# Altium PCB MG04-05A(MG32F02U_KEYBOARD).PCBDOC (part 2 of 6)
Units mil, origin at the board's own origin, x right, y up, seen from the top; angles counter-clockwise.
Board outline 17912.8 x 10422.68 mil, 2 copper layers (Top Layer, Bottom Layer); 623 components, 347 nets, 1816 pads, 821 vias.
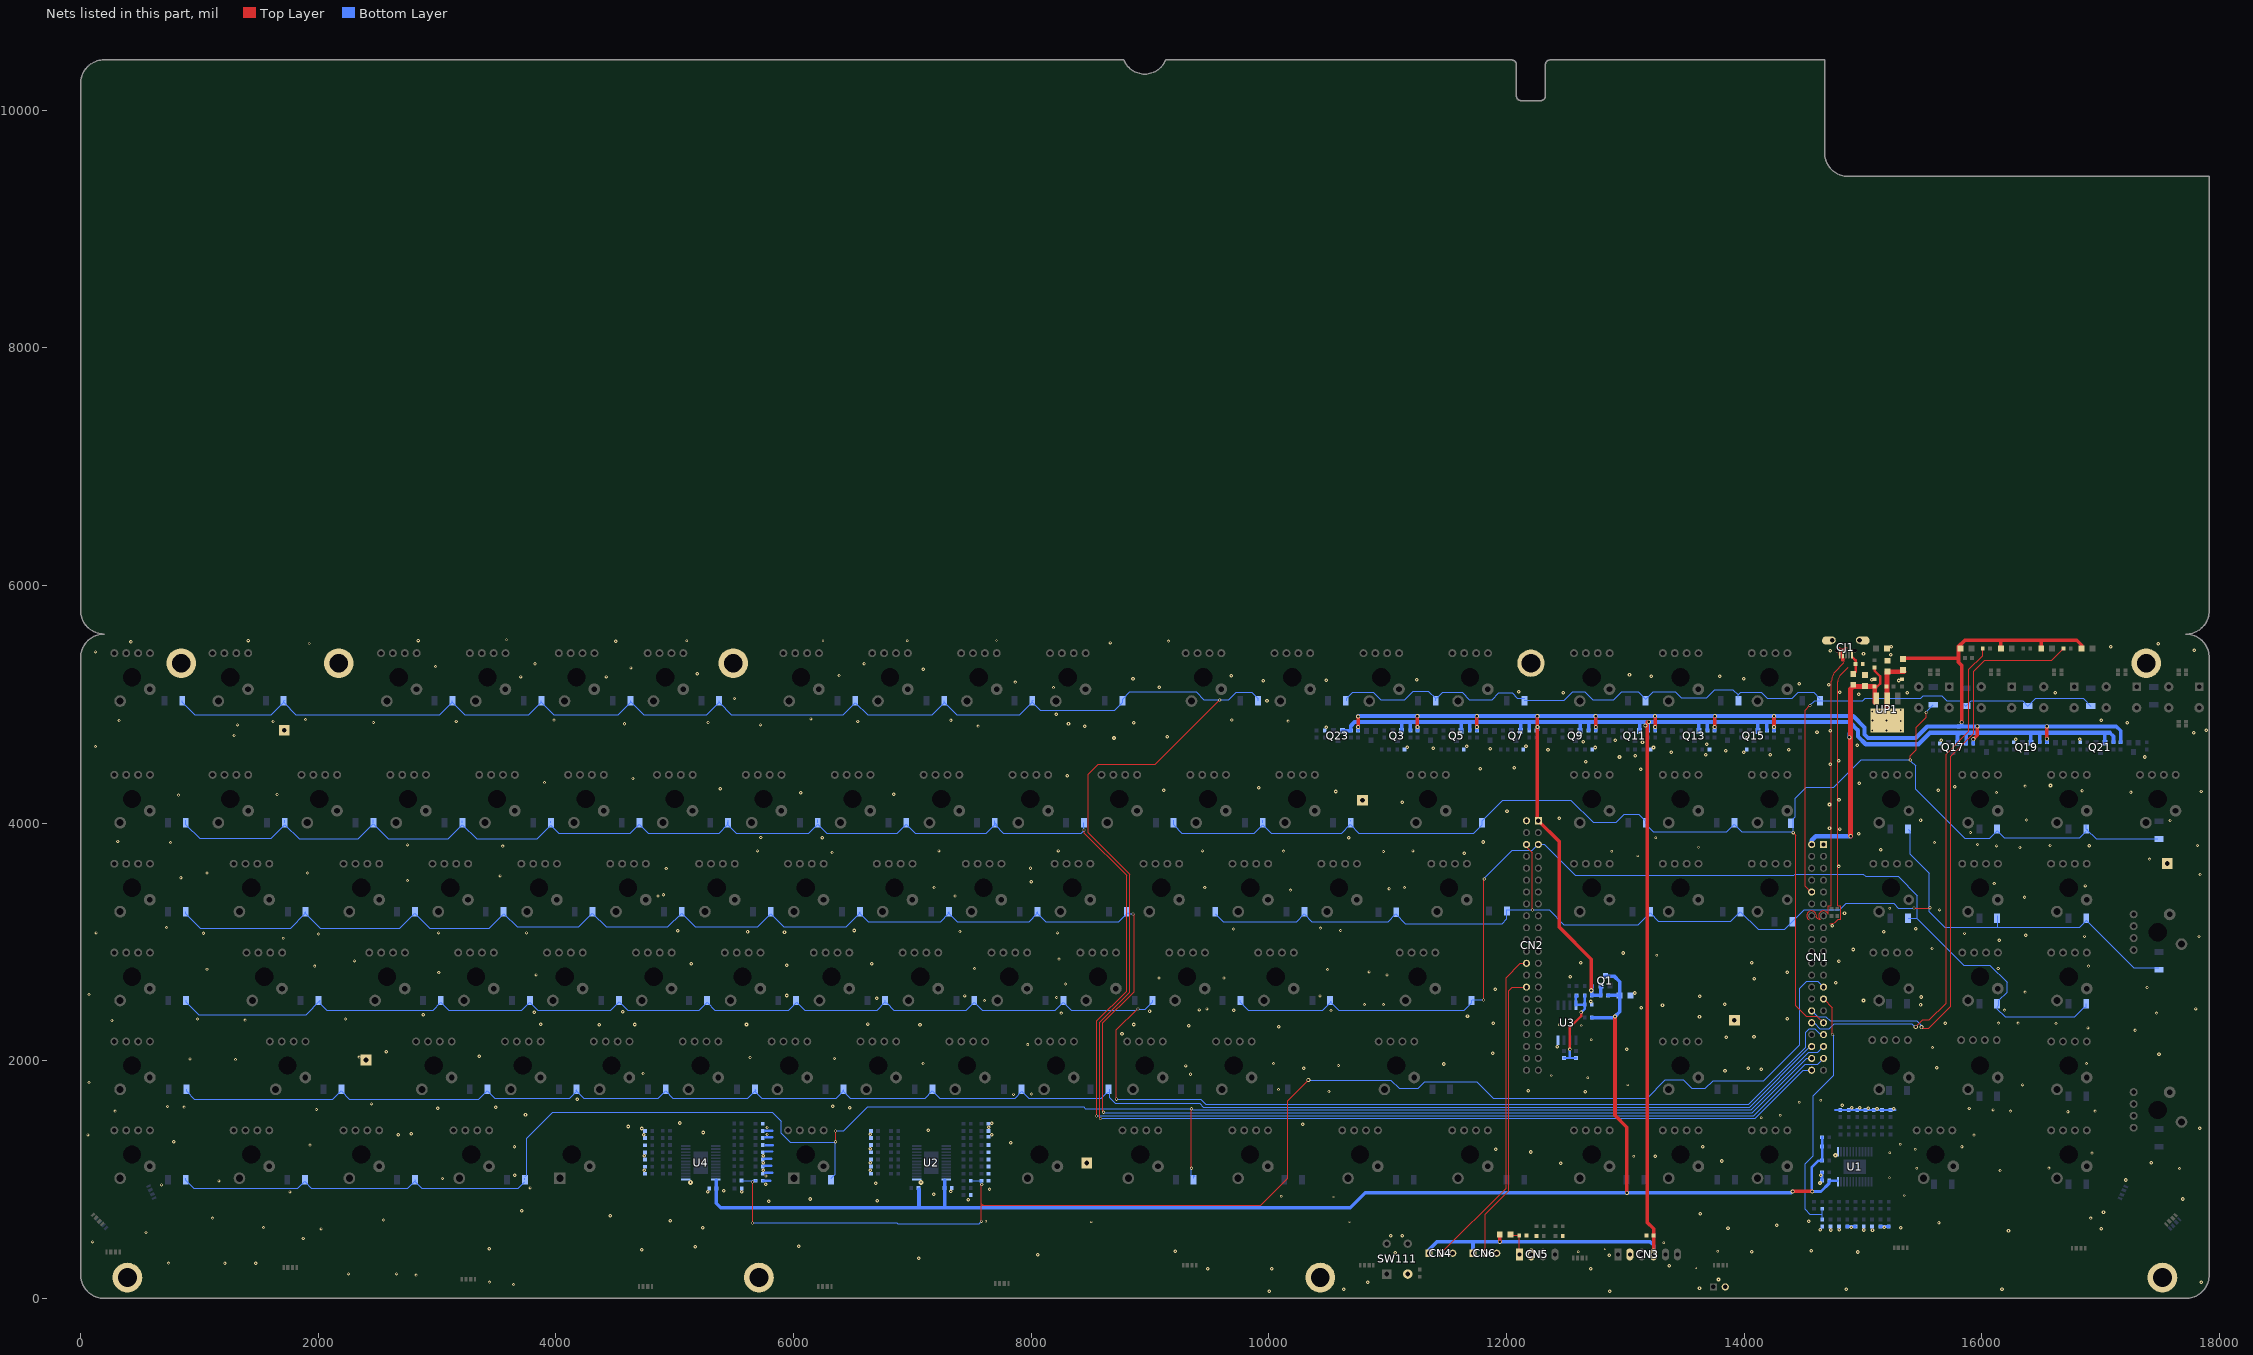
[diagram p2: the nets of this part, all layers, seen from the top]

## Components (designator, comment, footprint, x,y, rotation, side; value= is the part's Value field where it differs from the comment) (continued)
SW72 "SW_PB_SPST" SW2_KS4B#1 13463.65,4203.29 r0 top locked (schematic designator Home)
SW73 "SW_PB_SPST" SW2_KS4B#1 14211.65,4203.29 r0 top locked (schematic designator "Page Up")
SW74 "SW_PB_SPST" SW2_KS4B#1 15983.52,4203.29 r0 top locked (schematic designator N/)
SW75 "SW_PB_SPST" SW2_KS4B#1 16731.35,4203.29 r0 top locked (schematic designator N*)
SW76 "SW_PB_SPST" SW2_KS4B#1 17479.41,4203.29 r0 top locked (schematic designator N-)
SW77 "SW_PB_SPST" SW2_KS4B#1 9093.57,3454.89 r0 top locked (schematic designator P)
SW78 "SW_PB_SPST" SW2_KS4B#1 9841.6,3454.89 r0 top locked (schematic designator [{)
SW79 "SW_PB_SPST" SW2_KS4B#1 10589.63,3454.89 r0 top locked (schematic designator ]})
SW80 "SW_PB_SPST" SW2_KS4B#1 11514.79,3454.89 r0 top locked (schematic designator \)
SW81 "SW_PB_SPST" SW2_KS4B#1 12715.58,3454.89 r0 top locked (schematic designator Delete)
SW82 "SW_PB_SPST" SW2_KS4B#1 13463.65,3454.89 r0 top locked (schematic designator END)
SW83 "SW_PB_SPST" SW2_KS4B#3 14211.65,3454.89 r0 top locked (schematic designator "Page Down")
SW84 "SW_PB_SPST" SW2_KS4B#3 15235.27,4203.29 r0 top locked (schematic designator "Num Lock")
SW85 "SW_PB_SPST" SW2_KS4B#1 15983.34,3454.89 r0 top locked (schematic designator N8)
SW86 "SW_PB_SPST" SW2_KS4B#1 16730.57,3454.89 r0 top locked (schematic designator N9)
SW87 "SW_PB_SPST" SW2_KS4B#1 17479.6,3081.25 r90 top (schematic designator N+)
SW88 "SW_PB_SPST" SW2_KS4B#1 9310.11,2707.29 r0 top locked (schematic designator ;:)
SW89 "SW_PB_SPST" SW2_KS4B#1 10058.14,2707.29 r0 top locked (schematic designator "'\"")
SW90 "SW_PB_SPST" SW2_KS4B#1 11249.08,2707.29 r0 top locked (schematic designator Enter)
SW91 "SW_PB_SPST" SW2_KS4B#3 15234.49,3454.89 r0 top locked (schematic designator N7)
SW92 "SW_PB_SPST" SW2_KS4B#1 15983.52,2707.29 r0 top locked (schematic designator N5)
SW93 "SW_PB_SPST" SW2_KS4B#1 16731.57,2707.29 r0 top locked (schematic designator N6)
SW94 "SW_PB_SPST" SW2_KS4B#1 8955.75,1959.19 r0 top locked (schematic designator .>)
SW95 "SW_PB_SPST" SW2_KS4B#1 9703.78,1959.19 r0 top locked (schematic designator /1)
SW96 "SW_PB_SPST" SW2_KS4B#1 11071.89,1959.19 r0 top locked (schematic designator R-SHIFT)
SW97 "SW_PB_SPST" SW2_KS4B#1 13463.65,1959.19 r0 top locked (schematic designator UP-L)
SW98 "SW_PB_SPST" SW2_KS4B#3 15234.84,2707.29 r0 top locked (schematic designator N4)
SW99 "SW_PB_SPST" SW2_KS4B#1 15983.5,1959.19 r0 top locked (schematic designator N2)
SW100 "SW_PB_SPST" SW2_KS4B#1 16731.36,1959.19 r0 top locked (schematic designator N3)
SW101 "SW_PB_SPST" SW2_KS4B#1 17479.4,1585.19 r90 top locked (schematic designator N-Enter)
SW102 "SW_PB_SPST" SW2_KS4B#1 9840.58,1211.19 r0 top locked (schematic designator FN)
SW103 "SW_PB_SPST" SW2_KS4B#1 10765.78,1211.19 r0 top locked (schematic designator APP)
SW104 "SW_PB_SPST" SW2_KS4B#1 11690.98,1211.19 r0 top locked (schematic designator R-Ctrl)
SW105 "SW_PB_SPST" SW2_KS4B#1 12715.58,1211.19 r0 top locked (schematic designator Left-L)
SW106 "SW_PB_SPST" SW2_KS4B#1 13463.65,1211.19 r0 top locked (schematic designator Down-L)
SW107 "SW_PB_SPST" SW2_KS4B#1 14211.65,1211.19 r0 top locked (schematic designator Right-L)
SW108 "SW_PB_SPST" SW2_KS4B#1 15235.47,1959.19 r0 top locked (schematic designator N1)
SW109 "SW_PB_SPST" SW2_KS4B#1 15609.49,1211.19 r0 top locked (schematic designator N0)
SW110 "SW_PB_SPST" SW2_KS4B#1 16731.54,1211.19 r0 top locked (schematic designator .DEL)
SW111 "SW1_4P" SW-TACT-P4.5X6.5-Z6.2X6.2X5#2 10991,204.63 r90 bottom locked
SW112 "SW_PB_SPST" SW2_KS4B#2 4132.9,1211.19 r0 top locked (schematic designator Space3)
SW113 "SW_PB_SPST" SW2_KS4B#1 8069.91,1211.19 r0 top locked (schematic designator Space2)
TP1 "TP-Gold" SIP1-39 2401.17,2006.36 r0 top
TP2 "TP-Gold" SIP1-39 1712.2,4781.95 r0 top
TP3 "TP-Gold" SIP1-39 8467,1140 r0 top
TP4 "TP-Gold" SIP1-39 17558.66,3659.9 r0 top
TP5 "TP-Gold" SIP1-39 13916.92,2341 r0 top
TP6 "TP-Gold" SIP1-39 10787,4191.4 r0 top
U1 "TLC5948A" SOP24-P0.65-W6.4-PAD 14789.25,1234.89 r0 bottom locked
U2 "TLC5948A" SOP24-P0.65-W6.4-PAD 7034.02,999.89 r90 bottom locked
U3 "MX25LXX-SOP" SOP8-P1.27-W6.2+8.1 12583.22,2171.26 r180 bottom
U4 "TLC5948A" SOP24-P0.65-W6.4-PAD 5094.02,999.89 r90 bottom locked
UP1 "AP1117-ADJ" SOT223H\3P 15202,4920 r180 top

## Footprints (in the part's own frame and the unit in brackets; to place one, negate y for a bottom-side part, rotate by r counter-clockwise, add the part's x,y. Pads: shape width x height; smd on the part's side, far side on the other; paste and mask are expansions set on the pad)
C-0603 [mil]
  rect 32x32 smd: 1(-30,0) 2(30,0)
  silkscreen extent -60,-26 60,26
C-0805 [mil]
  rect 50x50 smd: 1(-46,0) 2(46,0)
  silkscreen extent -90,-40 90,40
D-0805 [mil]
  rect 50x50 smd: 1(0,46) 2(0,-46)
  silkscreen extent -40,-85 40,85
DIODE_DO213AA [mm]
  rect 1.25x2 smd: 1(-1.9,0) 2(1.9,0)
  silkscreen extent -2.6,-1.1 3,1.1
HD4-P2.54-Z12.4X5.7X7-UL [mil]
  rect 60x100 hole 35: 1(-150,0)
  oval 60x100 hole 35: 2(-50,0) 3(50,0) 4(150,0)
  silkscreen extent -246,-130 245,118
HD6-P2.54-UL [mil]
  rect 60x100 hole 35: 1(-250,0)
  oval 60x100 hole 35: 2(-150,0) 3(-50,0) 4(50,0) 5(150,0) 6(250,0)
  silkscreen extent -344,-130 346,127
HD20X2-P2.54 [mil]
  rect 60x60 hole 37: 1(0,0)
  round 60 hole 37: 2(0,100) 3(100,0) 4(100,100) 5(200,0) 6(200,100) 7(300,0) 8(300,100) 9(400,0) 10(400,100) 11(500,0) 12(500,100) 13(600,0) 14(600,100) 15(700,0) 16(700,100) 17(800,0) 18(800,100) 19(900,0) 20(900,100) 21(1000,0) 22(1000,100) 23(1100,0) 24(1100,100) 25(1200,0) 26(1200,100) 27(1300,0) 28(1300,100) 29(1400,0) 30(1400,100) 31(1500,0) 32(1500,100) 33(1600,0) 34(1600,100) 35(1700,0) 36(1700,100) 37(1800,0) 38(1800,100) 39(1900,0) 40(1900,100)
  silkscreen extent -50,-73 1960,150
HD22X2-P2.54 [mil]
  rect 60x60 hole 37: 1(0,0)
  round 60 hole 37: 2(0,100) 3(100,0) 4(100,100) 5(200,0) 6(200,100) 7(300,0) 8(300,100) 9(400,0) 10(400,100) 11(500,0) 12(500,100) 13(600,0) 14(600,100) 15(700,0) 16(700,100) 17(800,0) 18(800,100) 19(900,0) 20(900,100) 21(1000,0) 22(1000,100) 23(1100,0) 24(1100,100) 25(1200,0) 26(1200,100) 27(1300,0) 28(1300,100) 29(1400,0) 30(1400,100) 31(1500,0) 32(1500,100) 33(1600,0) 34(1600,100) 35(1700,0) 36(1700,100) 37(1800,0) 38(1800,100) 39(1900,0) 40(1900,100) 41(2000,0) 42(2000,100) 43(2100,0) 44(2100,100)
  silkscreen extent -50,-73 2160,150
L-0603 [mil]
  rect 32x32 smd: 1(-30,0) 2(30,0)
  silkscreen extent -55,-25 55,25
LED4P_SMD_1.6X1.6_CRGB [mm]
  rect 0.7x0.9 smd: 1(-0.425,-0.8) 2(-0.425,0.8) 3(0.425,0.8) 4(0.425,-0.8)
  silkscreen extent -0.94,-0.89 0.8,0.97
LED4P_SMD_3X1_CRGB [mm]
  rect 0.7x1 smd: 1(0.508,-0.262) 2(-0.508,-0.262)
  rect 0.5x1 smd: 3(1.4,-0.262) 4(-1.4,-0.262)
  silkscreen extent -1.5,-0.5 1.5,0.51
LED-0805 [mil]
  rect 50x50 smd: 1(0,48) 2(0,-44)
  silkscreen extent -40,-83 40,87
LED_3.5_CRGB [mm]
  round 1.7 hole 1: 1(-1.27,0) 2(1.27,0) 3(-3.81,0) 4(3.81,0)
  silkscreen extent -3.65,-1.75 3.65,1.75
MEGAWIN_4.9 [mil]
  silkscreen extent 18,8 399,198
R-0603 [mil]
  rect 32x32 smd: 1(-30,0) 2(30,0)
  silkscreen extent -56,-26 56,26
SCREW1-H4-R6.35#1 [mm]
  round 6.35 hole 4: 1(0,0)
SCREW1-H4-R6.35#2 [mm]
  round 5.842 hole 4: 1(0,0)
SIP1-39 [mil]
  rect 90x90 hole 39: 1(0,0)
  silkscreen extent -51,-51 51,51
SIP2-P2.54 [mil]
  rect 60x60 hole 37: 1(0,0)
  round 60 hole 37: 2(100,0)
  silkscreen extent -50,-50 150,50
SIP3-P2.54 [mil]
  rect 60x60 hole 37: 1(0,0)
  round 60 hole 37: 2(100,0) 3(200,0)
  silkscreen extent -50,-68 250,50
SOP8-P1.27-W6.2+8.1 [mil]
  rect 24x80 smd: 1(0,0) 2(50,0) 3(100,0) 4(150,0) 5(150,295.28) 6(100,295.28) 7(50,295.28) 8(0,295.28)
  silkscreen extent -30,53 183,244
SOP24-P0.65-W6.4-PAD [mm]
  rect 0.4x2.032 smd: 1(0,0) 2(0.65,0) 3(1.3,0) 4(1.95,0) 5(2.6,0) 6(3.25,0) 7(3.9,0) 8(4.55,0) 9(5.2,0) 10(5.85,0) 11(6.5,0) 12(7.15,0) 13(7.15,6.4) 14(6.5,6.4) 15(5.85,6.4) 16(5.2,6.4) 17(4.55,6.4) 18(3.9,6.4) 19(3.25,6.4) 20(2.6,6.4) 21(1.95,6.4) 22(1.3,6.4) 23(0.65,6.4) 24(0,6.4)
  rect 4.8x3.1 smd: 25(3.575,3.2)
  silkscreen extent -0.65,1.3 7.8,5.08
SOT223H\3P [mil]
  rect 45x100 smd: 1(-91,-128) 2(0,-128) 3(91,-128)
  rect 283x204 smd: 4(0,56)
  silkscreen extent -150,-53 150,72
SOT-23 [mil]
  rect 42x50 smd: 1(37.4,36) 2(-37.4,36) 3(0,-42.74)
  silkscreen extent -72,-76 72,72
SW2_KS4B#1 [mm]
  round 3 hole 3.9 unplated: 0(0,0)
  round 2.5 hole 1.5: 1(-2.54,-5.08)
  round 2.5 hole 1.2: 2(3.81,-2.54)
  silkscreen extent -7,-7.8 7,7.8
SW2_KS4B#2 [mm]
  round 3 hole 3.9 unplated: 0(0,0)
  rect 2.5x2.5 hole 1.5: 1(-2.54,-5.08)
  round 2.5 hole 1.2: 2(3.81,-2.54)
  silkscreen extent -7,-7.8 7,7.8
SW2_KS4B#3 [mm]
  round 3 hole 3.9 unplated: 0(0,0)
  round 2.5 hole 1.5: 1(-2.54,-5.08)
  round 2.235 hole 1.2: 2(3.81,-2.54)
  silkscreen extent -7,-7.8 7,7.8
SW-TACT-P4.5X6.5-Z6.2X6.2X5#1 [mil]
  rect 70x70 / inner rect 80x80 / far side rect 80x80 hole 40: 1(0,0)
  round 80 hole 40: 2(0,177) 3(256,0) 4(256,177)
  silkscreen extent 25,0 225,175
SW-TACT-P4.5X6.5-Z6.2X6.2X5#2 [mil]
  rect 70x70 / inner rect 80x80 / far side rect 80x80 hole 40: 1(0,0)
  round 80 hole 40: 2(0,177)
  round 70 hole 40: 3(256,0) 4(256,177)
  silkscreen extent 25,0 225,175
USB5A-MICRO-290X220P065 [mm]
  rect 2x0.4 smd: 1(0,1.3)
  oval 2x0.4 smd: 2(0,0.65) 3(0,0) 4(0,-0.65) 5(0,-1.3)
  round 1.524 hole 1: 6(-2.931,2.921) 7(-2.931,-2.921)
  oval 1.8x2.54 smd: 8(-2.85,3.826) 9(-2.85,-3.826)
  round 0.8 hole 0.9 unplated: 10(-0.7,1.9) 11(-0.7,-1.9)
  silkscreen extent -5.65,-4.25 -0.01,4.2

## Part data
C1 C3 C5: library part CAP-POL
C2 C4 C6 C7 C8 C9 C10 C11 C12 C13 C14 C15 C16 C17 C18 C19 C20 C21 C22 C23 C24 C25 C26 C27 C28 C29 C30 C31 C32 C33 C34 C35 C36 C37 C38 C39 C40 C41 C42 C43 C44 C45 C46 C47 C48 C49 C50 C51 C52 C53 C54 C55 C56 C57 C58 C59 C60 C61: library part CAP-NP
CN1: library part HEADER20X2
CN2: library part HEADER22X2
CN3: library part SIP6
CN4 CN6: library part HEADER3
CN5: library part SIP4
D1 D119 D120 D121 D122: library part LED
D2 D3 D123: library part DIODE-SCHOTTKY-2
D4 D5 D6 D7 D8 D9 D10 D11 D12 D13 D14 D15 D16 D17 D18 D19 D20 D21 D22 D23 D24 D25 D26 D27 D28 D29 D30 D31 D32 D33 D34 D35 D36 D37 D38 D39 D40 D41 D42 D43 D44 D45 D46 D47 D48 D49 D50 D51 D52 D53 D54 D55 D56 D57 D58 D59 D60 D61 D62 D63 D64 D65 D66 D67 D68 D69 D70 D71 D72 D73 D74 D75 D76 D77 D78 D79 D80 D81 D82 D83 D84 D85 D86 D87 D88 D89 D90 D91 D92 D93 D94 D95 D96 D97 D98 D99 D100 D101 D102 D103 D104 D105 D106 D107 D108 D109 D110 D111 D112 D113 D114 D115 D116 D117 D118: library part DIODE
DD1 DD2 DD3 DD4 DD5 DD6 DD7 DD8 DD9 DD10 DD11 DD12 DD13 DD14 DD15 DD16 DD17 DD18: library part LED-4P-CRGB3
FB1 FB2 FB3 FB4: library part FB2
G1 G2 G3 G4 G5 G6 G7 G8 G10: library part ScrewPad-1P, "MTG HOLE;ID2.5,OD6.6,NPTH,12 VIA"
G9 G11: library part LOGO-Megawin_3_4
HK1 HK2 HK3 LOGO1 MUTE1: library part SW-PB-4P2
KD1 KD2 KD3 KD4 KD5 KD6 KD7 KD8 KD9 KD10 KD11 KD12 KD13 KD14 KD15 KD16 KD17 KD18 KD19 KD20 KD21 KD22 KD23 KD24 KD25 KD26 KD27 KD28 KD29 KD30 KD31 KD32 KD33 KD34 KD35 KD36 KD37 KD38 KD39 KD40 KD41 KD42 KD43 KD44 KD45 KD46 KD47 KD48 KD49 KD50 KD51 KD52 KD53 KD54 KD55 KD56 KD57 KD58 KD59 KD60 KD61 KD62 KD63 KD64 KD65 KD66 KD67 KD68 KD69 KD70 KD71 KD72 KD73 KD74 KD75 KD76 KD77 KD78 KD79 KD80 KD81 KD82 KD83 KD84 KD85 KD86 KD87 KD88 KD89 KD90 KD91 KD92 KD93 KD94 KD95 KD96 KD97 KD98 KD99 KD100 KD101 KD102 KD103 KD104 KD105 KD106 KD107 KD108 KD109 KD110: library part LED-4P-CRGB
LED1 LED2 LED3 LED4 LED5 LED6: library part LED-4P-CRGB2
Q1 Q3 Q5 Q7 Q9 Q11 Q13 Q15 Q17 Q19 Q21 Q23: library part MOS-P-SOT23
Q2 Q4 Q6 Q8 Q10 Q12 Q14 Q16 Q18 Q20 Q22: library part MOS-N-SOT23
R1 R2 R3 R4 R5 R61 R62 R63 R82 R84 R86 R100 R101 R102 R109 R127 R128 R129: library part R
R6 R7 R8 R9 R10 R11 R12 R13 R14 R15 R16 R17 R18 R19 R20 R21 R22 R23 R24 R25 R26 R27 R28 R29 R30 R31 R32 R33 R34 R35 R36 R37 R38 R39 R40 R41 R42 R43 R44 R45 R46 R47 R48 R49 R50 R51 R52 R53 R54 R55 R56 R57 R58 R59 R60 R64 R65 R66 R67 R68 R69 R70 R71 R72 R73 R74 R75 R76 R77 R78 R79 R80 R81 R83 R85 R87 R88 R89 R91 R92 R93 R94 R95 R96 R97 R98 R103 R104 R105 R106 R110 R111 R112 R113 R114 R115 R116 R117 R118 R119 R120 R121 R122 R123 R124 R125 R126 R130: library part RES
R90 R99 R107 R108: library part R2X
SW1 SW2 SW3 SW4 SW5 SW6 SW7 SW8 SW9 SW10 SW11 SW12 SW13 SW14 SW15 SW16 SW17 SW18 SW19 SW20 SW21 SW22 SW23 SW24 SW25 SW26 SW27 SW28 SW29 SW30 SW31 SW32 SW33 SW34 SW35 SW36 SW37 SW38 SW39 SW40 SW41 SW42 SW43 SW44 SW45 SW46 SW47 SW48 SW49 SW50 SW51 SW52 SW53 SW54 SW55 SW56 SW57 SW58 SW59 SW60 SW61 SW62 SW63 SW64 SW65 SW66 SW67 SW68 SW69 SW70 SW71 SW72 SW73 SW74 SW75 SW76 SW77 SW78 SW79 SW80 SW81 SW82 SW83 SW84 SW85 SW86 SW87 SW88 SW89 SW90 SW91 SW92 SW93 SW94 SW95 SW96 SW97 SW98 SW99 SW100 SW101 SW102 SW103 SW104 SW105 SW106 SW107 SW108 SW109 SW110 SW112 SW113: library part SW-PB-2P-KB
SW111: library part SW-PB-4P
TP1 TP2 TP3 TP4 TP5 TP6: library part TPH-GND
U1 U2 U4: library part IC-TLC5948A
U3: library part ICM-25LXX
UP1: library part ICP-AP1117

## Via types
v1: diameter 30, hole 12, Top Layer to Bottom Layer, tented both sides, 273 vias
v2: diameter 26, hole 16, Top Layer to Bottom Layer, tented both sides, 181 vias
v3: diameter 26, hole 12, Top Layer to Bottom Layer, tented both sides, 165 vias
v4: diameter 33, hole 20, Top Layer to Bottom Layer, tented both sides, 61 vias
v5: diameter 25, hole 12, Top Layer to Bottom Layer, tented both sides, 47 vias
v6: diameter 20, hole 12, Top Layer to Bottom Layer, tented both sides, 40 vias
v7: diameter 30, hole 16, Top Layer to Bottom Layer, tented both sides, 30 vias
v8: diameter 28, hole 16, Top Layer to Bottom Layer, tented both sides, 12 vias
v9: diameter 35, hole 20, Top Layer to Bottom Layer, tented both sides, 5 vias
v10: diameter 25, hole 16, Top Layer to Bottom Layer, tented both sides, 3 vias
v11: diameter 40, hole 12, Top Layer to Bottom Layer, tented both sides, 3 vias
v12: diameter 40, hole 20, Top Layer to Bottom Layer, tented both sides, 1 vias

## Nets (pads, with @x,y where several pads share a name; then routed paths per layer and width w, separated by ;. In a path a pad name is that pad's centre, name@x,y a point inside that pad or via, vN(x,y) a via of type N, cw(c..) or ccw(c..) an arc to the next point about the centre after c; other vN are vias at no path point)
+3V3: CN2.1 D3.2 D119.1 D120.1 D121.1 D122.1 FB2.2 FB3.1 FB4.2 Q1.2 R3.2 R6.1 R11.1 R16.1 R21.1 R26.1 R31.1 R36.1 R41.1 R46.1 R51.1 R56.1 | length 12948.5
  Top Layer w30: v4@10750,4805 v4(10750,4808.48) v4(10750,4897.08) ; v4@11249,4806 v4(11249,4900.48) ; v4@11749,4806 v4(11749,4900.48) ; CN2.1@12259,4038 v4(12259,4900.48) ; CN2.1@12267,4020 12442,3845 12442,3125 12712,2855 v12(12712,2591.47) ; v4@12749,4806 v4(12749,4900.48) ; v4@13249,4806 v4(13249,4900.48) ; v4@13752.6,4808.48 v4(13752.6,4900.48) ; v4@14250,4805.41 v4(14250,4808.48) v4(14250,4900.48) ; D3.2@15334.25,5386 15803,5386 ; v4(15829.6,4848.48) 15829.6,5326.88 15803,5353.48 15803,5386 ; v4(15928,4706) 15961.41,4739.41 v4@15961.41,4813.48 ; D120.1@16159,5470 16159,5538 ; D121.1@16499,5470 16499,5538 ; v4(16547,4710) v4@16547,4812.48 ; D122.1@16839,5470 16839,5498 16797,5540 15857,5540 15803,5486 15803,5386
  Bottom Layer w30: R56.1@10750,4780 v4(10750,4808.48) ; R6.1@11250,4780 v4(11250,4808.48) ; R11.1@11750,4780 v4(11750,4808.48) ; R16.1@12260,4780 v4(12260,4808.48) ; R3.2@12717,2630 FB4.2@12717,2550 FB2.2@12777,2550 ; R21.1@12750,4780 v4(12750,4808.48) ; FB2.2@12792,2550 12792,2631.4 Q1.2@12794.6,2634 ; R26.1@13250,4780 v4(13250,4808.48) ; R31.1@13750,4780 v4(13750,4808.48) ; R36.1@14250,4780 v4(14250,4808.48) ; 15829.6,4814.03 v4(15829.6,4848.48) ; R41.1@15927,4670 v4@15927,4707.3 ; R46.1@16547,4680 v4(16547,4710) ; 17129.6,4813.48 17167,4776.08 R51.1@17167,4680
  Bottom Layer w35: v4@10750,4900.48 v4(11249,4900.48) v4(11749,4900.48) v4(12259,4900.48) v4(12749,4900.48) v4(13249,4900.48) v4(13752.6,4900.48) v4(14250,4900.48) 14917.06,4900.48 15011.85,4805.7 15011.85,4744.7 15039.85,4716.7 15442.85,4716.7 15539.64,4813.48 v4(16546,4813.48) 17129.6,4813.48
  other v4: 15961.41,4814.48
+3V3_FS: C36.1 FB4.1 R100.1 R101.1 R102.1 U3.8 | length 832.7
  Top Layer w20: v7(12532,2095) 12532,2280 12627,2375 v7(12627,2406.47)
  Bottom Layer w20: R100.1@12483.22,2022.74 12532,2022.74 ; v7(12532,2095) 12532,2022.74 ; R101.1@12583.22,2022.74 12532,2022.74 ; U3.8@12583.22,2466.54 R102.1@12583.22,2543.78 ; R102.1@12587,2550 R102.1@12593.22,2543.78 ; U3.8@12589.42,2472.74 C36.1@12657,2472.74 ; v7(12627,2406.47) 12657,2436.47 C36.1@12657,2472.74 ; FB4.1@12657,2550 C36.1@12657,2472.74
+3V3_LDO: C5.1 D3.1 R4.1 UP1.2 UP1.4 | length 547.6
  Top Layer w40: UP1.4@15202,4864 v7(15202,4950.7) UP1.2@15202,5048 C5.1@15202,5274 ; C5.1@15207,5274 D3.1@15344.6,5274
  other v7: 15076.85,4780.7 15196.85,4780.7 15316.85,4780.7 15316.85,4860.7 15077.85,4862.7 15197,4864 15076.85,4940.7 15316.85,4950.7
+5V: C3.1 C4.1 CN1.2 D2.2 FB1.1 R1.1 UP1.3 | length 2200.5
  Top Layer w20: R1.1@15097,5310 15097,5282.6 15144.6,5235 15144.6,5173.48 C4.1@15109.6,5138.48
  Top Layer w40: v4(14894.6,3890) 14894.6,5127.82 14916.78,5150 C4.1@15097,5150 UP1.3@15097,5014.47
  Bottom Layer w35: v4(14884.85,4721.45) FB1.1@14884.85,4753.7
  Bottom Layer w40: CN1.2@14567,3820 14567,3855.88 14601.12,3890 v4(14894.6,3890)
+5V_USB: C2.1 CJ1.1 CJ1.10 D2.1 | length 172.7
  Top Layer w20: CJ1.1@14906.18,5431.89 CJ1.1@14906.18,5424.1 14906.18,5400 14937,5369.18 C2.1@14937,5340 D2.1@14937,5272
+VDD_DRV: C1.1 C6.1 C23.1 C41.1 FB2.1 Q1.3 R61.1 R62.1 R63.1 R82.1 R109.1 U1.24 U2.24 U4.24 | length 12928.7
  Top Layer w30: v4(12912,2372.74) 12912,1540 13012,1440 v4(13012,887.82) ; v4(14407,900.05) v4(14572,900.05)
  Bottom Layer w20: v4@14567,910.05 14567,1102.74 14624.16,1159.9 R63.1@14654.64,1159.9 R62.1@14654.64,1278.01 R61.1@14654.64,1356.75 ; C6.1@14714.64,989.89 U1.24@14785,989.89
  Bottom Layer w25: v4(14572,900.05) 14645.58,900.05 14714.64,969.1 C6.1@14714.64,989.89
  Bottom Layer w30: U4.24@5350,995.87 C41.1@5350,924.89 5350,799.89 5386.4,763.48 7055,763.48 ; R82.1@7055,919.89 7055,763.48 ; U2.24@7270,994.89 C23.1@7270,929.89 7270,763.48 ; R109.1@12717,2362.74 12902,2362.74 v4@12922.46,2383.2 ; Q1.3@12832,2712.74 12904.26,2712.74 12951,2666 C1.1@12951,2550 ; FB2.1@12852,2550 C1.1@12951,2550 ; v4(12912,2372.74) 12951,2411.74 C1.1@12951,2550 ; C1.1@12952,2550 C1.1@12951,2550 ; v4(14407,900.05) 14394.77,887.82 v4(13012,887.82) 10808.97,887.82 10684.64,763.48 7270,763.48 ; 7055,763.48 7270,763.48
+VDD_LED: C58.1 CN3.4 CN4.1 CN6.1 D123.1 FB1.2 FB3.2 Q3.2 Q5.2 Q7.2 Q9.2 Q11.2 Q13.2 Q15.2 Q17.2 Q19.2 Q21.2 Q23.2 R7.1 R12.1 R17.1 R22.1 R27.1 R32.1 R37.1 R42.1 R47.1 R52.1 R57.1 | length 14919.9
  Top Layer w30: CN4.1@11347,365.7 CN4.1@11347,380 ; D123.1@11942,536.47 11942,481.47 v4@11944.5,478.97 ; v4(13197,4851.47) 13183.47,4851.47 13182,4850 13182,641.08 13237,586.08 C58.1@13237,530 CN3.4@13237,370
  Bottom Layer w30: Q23.2@10617.4,4777 10687,4777 R57.1@10690,4780 10690,4819 ; Q3.2@11115,4771.4 Q3.2@11115,4776 ; Q3.2@11117.4,4776 11117.4,4850 ; R7.1@11190,4780 11190,4850 ; CN4.1@11347,380 11347,410 11413.47,476.47 11717,476.47 ; Q5.2@11617.4,4776 Q5.2@11620,4778.6 ; Q5.2@11620,4771.4 Q5.2@11620,4778.6 ; 11620,4850 Q5.2@11620,4778.6 ; Q5.2@11621.4,4780 Q5.2@11620,4778.6 ; R12.1@11690,4780 11690,4845 ; CN6.1@11717,380 11717,476.47 ; Q7.2@12119.6,4776 12119.6,4850 ; R17.1@12189.6,4795 12189.6,4850 ; 12227,476.47 12247,476.47 ; Q9.2@12620,4778.6 12620,4850 ; R22.1@12690,4780 12690,4850 ; Q11.2@13120,4771.4 13120,4850 ; R27.1@13190,4780 v4@13190,4850 ; CN3.4@13237,370 13237,446.47 13207,476.47 12247,476.47 ; Q13.2@13617.4,4776 13617.4,4850 ; R32.1@13690,4780 13690,4845 ; Q15.2@14115,4765 14115,4850 ; R37.1@14190,4780 14190,4850 ; Q17.2@15794.4,4676 FB3.2@15794.4,4750 ; R42.1@15867,4670 15867,4760 ; Q19.2@16411,4676.31 16411,4760 ; R47.1@16487,4680 16487,4760 ; Q21.2@17034.4,4676 17034.4,4760 ; 17077,4760 17107,4730 R52.1@17107,4680 ; 11717,476.47 v4(11942,476.47) 12247,476.47
  Bottom Layer w35: 10690,4819 10721,4850 14887.55,4850 14956.85,4780.7 14956.85,4728.3 15021.94,4663.21 15465,4663.21 15561.79,4760 15867,4760 16411,4760 16487,4760 17034.4,4760 17077,4760
  other v4: 13167,4821.47
+VDD_UART0: C59.1 CN5.1 D123.2 | length 247.7
  Top Layer w8: D123.2@12022,536.47 12028.47,530 C59.1@12107,530 CN5.1@12107,370
ARGB_0: CN2.26 CN4.2 | length 2768
  Top Layer w8: CN4.2@11447,380 11995.15,928.15 11995.15,2699 12116.15,2820 CN2.26@12167,2820
ARGB_1: CN2.30 CN6.2 | length 2495.4
  Top Layer w8: CN6.2@11809.6,368.48 11819.06,377.94 11819.06,708.52 12016,905.47 12016,2590 12046,2620 CN2.30@12167,2620 CN2.30@12167,2645
CAPSLOCK: CN1.32 R99.2 | length 4378.2
  Top Layer w8: v9@15439.03,2280.54 15503.49,2345 15558.3,2345 15697.98,2484.68 15697.98,4580.02 15889.6,4771.64 15889.6,5292.6 16007,5410 R99.2@16007,5470
  Bottom Layer w8: CN1.32@14567,2320 14587,2320 14637,2270 14717,2270 14756.8,2309.8 15409.77,2309.8 v9@15439.03,2280.54
  other v9: 15443.3,2284.8
GAME: CN1.30 R108.2 | length 5040.9
  Top Layer w8: v9@15498.53,2272.8 15552.67,2272.8 15737.98,2458.11 15737.98,4563.45 15929.6,4755.07 15929.6,5276.03 16023.57,5370 16587,5370 R108.2@16687,5470
  Bottom Layer w8: CN1.30@14567,2420 14617,2370 14687,2370 14722.39,2334.61 15452.54,2334.61 v9@15501.16,2285.99
  other v9: 15491.77,2282.8
GCLK_0: C24.1 C42.1 CN1.25 R85.2 R111.2 | length 11647.8
  Top Layer w8: v10(5655,633.48) v10@5655,974.89 ; v10(7580.53,649) 7580.53,773.48 ; v2@7580.53,958.48 7580.53,797.59 ; 7591.08,787.04 7580.53,797.59 ; v9(10332,1837.74) 10156.85,1662.59 10156.85,1010.7 9931.85,785.7 7592.75,785.7 ; 7580.53,773.48 7580.53,785.7 ; 7580.53,773.48 7592.75,785.7 ; 7580.53,785.7 7592.75,785.7 ; 7580.53,785.7 7580.53,797.59
  Bottom Layer w8: R111.2@5563.58,991.39 5687.58,991.39 C42.1@5678.97,1000 ; v10@5651,638.47 6868,638.47 6877,629.47 7561,629.47 v10(7580.53,649) ; R85.2@7497.46,991.8 C24.1@7580,991.8 ; v2@7580,961.77 C24.1@7580,989.89 ; v9(10332,1837.74) 11027,1837.74 11097,1767.74 11254.74,1767.74 11309.74,1822.74 11750.73,1822.74 11887,1686.47 13182,1686.47 13334.19,1838.66 13486.21,1838.66 13557.13,1767.74 13672,1767.74 13737,1832.74 14163.27,1832.74 14467.25,2136.72 14467.25,2610.25 14527,2670 14617,2670 CN1.25@14667,2620
  other v2: 7583.29,958.48
  other v10: 5655,979.89
GCLK_1: C7.1 CN1.27 R65.2 | length 2165.3
  Top Layer w8: CN1.27@14667,2520 14742.35,2444.66 v2(14742.35,2219.8)
  Bottom Layer w8: C7.1@14656,663.89 14656,710 ; R65.2@14656,753.89 14656,710 ; v2(14742.35,2219.8) 14752,2210.15 ; v2@14752.35,2219.8 14752.35,1876.69 14579.6,1703.94 14579.6,1201.25 14511.6,1133.25 14511.6,750.4 14552,710 14656,710
GND: C1.2 C2.2 C3.2 C4.2 C5.2 C6.2 C7.2 C8.2 C9.2 C10.2 C11.2 C12.2 C13.2 C14.2 C15.2 C16.2 C17.2 C18.2 C19.2 C20.2 C21.2 C22.2 C23.2 C24.2 C25.2 C26.2 C27.2 C28.2 C29.2 C30.2 C31.2 C32.2 C33.2 C34.2 C35.2 C36.2 C37.2 C38.2 C39.2 C40.2 C41.2 C42.2 C43.2 C44.2 C45.2 C46.2 C47.2 C48.2 C49.2 C50.2 C51.2 C52.2 C53.2 C54.2 C55.2 C56.2 C57.2 C58.2 C59.2 C60.2 C61.2 CJ1.4 CJ1.5 CJ1.6 CJ1.7 CJ1.8 CJ1.9 CJ1.11 CN1.1 CN2.2 CN3.2 CN4.3 CN5.2 CN6.3 D1.2 G1.1 G2.1 G3.1 G4.1 G5.1 G6.1 G7.1 G8.1 G10.1 JP1.2 R5.2 R9.1 R14.1 R19.1 R24.1 R29.1 R34.1 R39.1 R44.1 R49.1 R54.1 R59.1 R64.2 R83.2 R110.2 SW111.2 TP1.1 TP2.1 TP3.1 TP4.1 TP5.1 TP6.1 U1.1 U2.1 U3.4 U4.1 | length 6422.2
  Top Layer w8: 14544.77,3185.55 cw(c14567,3220) 14608,3220 cw(c14567,3220) 14605.54,3206.02 ccw(c14658.42,3270) 14640.12,3189.04 cw(c14667,3220) 14705.23,3234.8 ; 14705.87,3234.8 14705.87,3304.8 14733.78,3304.8 14733.78,5195.48 cw(c14850.78,5195.48) 14768.05,5278.21 ; 14718.72,3153 ccw(c14718.72,3238.28) 14779.02,3177.98 ; 14768.07,5278.23 14830.2,5340.36 ; 14779.04,3178 14791.85,3190.8 14809.87,3190.8 14809.87,3304.8 14785.78,3304.8 14785.78,5188.03 cw(c14868.78,5188.03) 14810.09,5246.71 ; 14810.11,5246.73 14876.12,5312.74 ; 14867.8,5469.48 ccw(c14855,5455.6) 14836.13,5455.6 14836.13,5392.61 ccw(c14855,5392.61) 14842.48,5378.48 14842.48,5370 ; 14830.21,5340.38 ccw(c14800.59,5370) 14842.48,5370 ; 14830.21,5340.38 ccw(c14800.59,5370) 14842.48,5370 ; 14830.21,5340.38 ccw(c14800.59,5370) 14842.48,5370
  Top Layer w20: CJ1.5@14801.17,5414.33 14801.17,5472.35 ; 14824.88,5371.54 14824.88,5462.35
  Bottom Layer w8: v1@14652.85,580.1 C7.2@14652.85,594.7
  Bottom Layer w15: 14763.3,1586.47 15272,1586.47
  Bottom Layer w20: C42.2@5743.3,990 C42.2@5753.58,990 ; C45.2@5750,1116.31 5810,1116.31 ; C47.2@5750,1176.31 5810,1176.31 ; C42.2@5753.58,991.39 C42.2@5753.58,990 ; 5760,1056.31 5820,1056.31 ; 5760,1236.31 5820,1236.31 ; 5760,1356.31 5820,1356.31 ; 5760,1411.39 5820,1411.39 ; 5763.3,1290 5823.3,1290 ; 5803.3,990 C42.2@5753.58,990
  Bottom Layer w25: C6.2@14654.64,992.74 R64.2@14654.64,1061.48 ; C12.2@14862.42,603.89 C15.2@14936,603.89 ; C20.2@15142.42,603.89 C22.2@15216,603.89
  other v1: 12867,60 10003.3,62 10631,76.31 16169,76.31 14859.3,77 13623.3,85 10832,136.31 17845,136.31 13783.3,159 10023.3,249 9483.3,250 12707,250 13368,276.31 7052,336.31 12863.3,362 8054,368 11063.3,386 14954,390.31 14063.3,393 9210,396.31 14563.3,402 4723.3,409 3440,416.31 5173,436.31 6043.3,440 11123.3,526 11024,528.47 16223.3,569 15079.3,574 14726,575.89 15006,575.89 14639.3,579 14799.3,579 17003.3,588 13863.3,589 5236.85,596.31 15318,596.31 14899.3,599 15179.3,599 14274,616.31 14543.3,650 4963.3,652 4458,696.31 13628.29,713.48 17023.3,724 3712,736.31 5791.85,816.31 6703.3,821.47 7468,831.89 6139,836.31 17689,836.31 7180,876.31 5277,896.31 5562,896.31 7323.3,900 5411.85,905.7 5767,960 6691.85,970.7 14637,971.47 17211,996.31 3652.11,1035.21 14643.3,1035 4743.3,1080 5743.3,1080 6643.3,1080 12455,1136.31 5743.3,1140 6643.3,1140 17423.3,1143 13810,1156.31 13249.6,1196.31 4743.3,1200 5743.3,1200 12203.3,1232 11909,1256.31 6643.3,1260 13649,1276.31 7826.85,1310.7 783.3,1320 2673,1376.31 4737,1376.31 7667,1376.31 6643.3,1380 2783.3,1385 5238.29,1396.31 7134,1416.31 4723.3,1430 7643.3,1440 4607,1446.47 10283.3,1467 7666.85,1475.7 5040,1476.31 3743.3,1544 15117,1596.31 15257,1596.31 15043.3,1600 3003.3,1601 14903.3,1605 14972,1605 6472,1606 3493,1608 6328,1616.31 14823.3,1625 4178,1676.31 12662,1737.74 12182,1747.74 13838,1916.31 14143.3,1928 10293,1936.31 14035,1936.31 15619.6,1941.25 11472,1972.74 3353,2036.31 17490,2056.31 11883.3,2062 2572,2076.31 13009.6,2096.31 12427,2117.74 13847,2196.31 14082,2202.74 8763.3,2229 10083.3,2286 9323.3,2295 7063.3,2301.47 4363.3,2304 4663.3,2305 5603.3,2305 8863.3,2305 3872,2306.47 6623.3,2309 11887,2316.31 15692.35,2316.31 14363.3,2353 13623.3,2370 11671,2376.31 2883.3,2386 3817,2406.47 4563.3,2411 8995,2416.31 9703.3,2426 13132,2445 13312,2467 15483.3,2469.8 13835,2476.31 12707,2498.74 15003.3,2507 15491,2536.31 13627,2541.47 5943.3,2549 13077,2570 11903.3,2603 14770,2656.31 14083.3,2689 12535,2706.31 14363.3,2744 5943.3,2805 5137,2816.31 6656,2816.31 12623.3,2825 14063.3,2825 14796.85,2836.31 12983.3,2907 14916.85,2936.31 5923.3,3081 15173,3085 5612,3086.47 5023.3,3093 6509,3096.31 14742,3136.31 14843.3,3240 14796.78,3635 11643.3,3745.7 15146.85,3776.31 11803.3,3840.7 10671.85,3876.31 14963.3,3910.7 14803.3,3950 14717,3956.31 15483.3,4025.7 12443.3,4040.7 12003.3,4100.7 14717,4156.31 11121.85,4176.31 14797,4196.31 6843.3,4244 6060,4256.31 10563.3,4265.7 9114,4276.31 15631.85,4276.31 5383.3,4288 9913,4296.31 15771.85,4305.7 16576.85,4316.31 14966.85,4336.31 8303.3,4399 13129.6,4453.48 11778,4456.31 12063.3,4466 14722.78,4496.31 12666.85,4516.31 14796.78,4525 12950,4556.31 17371,4556.31 13083.3,4565 13677,4576.31 14217,4576.31 13386,4596.31 13997,4596.31 13843.3,4610 12348,4616.31 14375,4616.31 11863.3,4625 11383.3,4630 12747,4636.31 13236,4636.31 11163.3,4640 11663.3,4645 12163.3,4645 14951.85,4656.31 13683.3,4665 13143.3,4682 12643.3,4685 12914,4696.31 15657,4696.31 16283.3,4705 16822,4706 8696,4716.31 14020,4716.31 9143.3,4727 17783.3,4762 14611.85,4765.7 14721.85,4775.7 17886.4,4783 10483.3,4805 8450,4816.31 8313,4836.31 17223.3,4845.7 8863.3,4846 17003.3,4865.7 9983.3,5028 14963.3,5085.7 12477,5096.31 15371.85,5096.31 16616,5096.31 14801.85,5100.7 12103.3,5106 9077.35,5144.8 14712,5165 14463.3,5172 9953,5196.31 15301.41,5200 10483.3,5201 15072,5205 11243.3,5207 8856,5216.31 13995,5216.31 13216,5236.31 13793,5236.31 9683.3,5241 13034,5248 5188,5256.31 7092,5296.31 15232,5416.31 15003.3,5425 14723.3,5450 17787,5456.31 17083.3,5483 15237,5485 17483.3,5508 423.3,5526 4503.3,5532 1412,5536.31 2840,5536.31
  other v3: 3643.3,115.81 2823.3,195.81 2253.3,205.81 2659.6,206.31 739.6,296.31 1213.3,295.81 1473.3,295.81 1873.3,505.81 2023.3,585.81 1539.6,596.31 15637,636.47 16915.6,676.31 7649.6,918.48 16153.3,1074.81 17663.3,1091.81 16563.3,1095.81 16926.54,1223 3649.6,1276.31 15830.6,1276.31 15933.3,1374.81 17833.3,1431.81 16723.3,1570.81 16239.6,1576.31 16951.85,1576.31 16094.6,1586.31 15893.3,1599.81 16342.6,1796.31 9340,1886.31 4733.3,1892.3 9300,1956.31 7089.63,1976.31 16879.6,1976.25 6343.3,2020 5633.3,2027.3 15583.3,2110.81 17288.6,2256.31 16891,2276.31 16623.3,2313 16139,2316.31 16304.6,2316.31 8252,2401.47 17469.6,2401.25 10522,2421.47 16191,2426 9413.3,2428.48 9477,2436.31 17799.6,2436.31 10803.3,2472.3 10963.3,2472.3 7604.63,2506.31 6699.63,2526.31 8213.3,2532.3 7439.63,2546.31 10429.63,2546.31 16363.3,2577.81 17389.6,2616.31 8286.43,2645.81 9074.63,2696.31 9620,2696.31 3833.3,2722.3 10993.3,2722.3 3013.3,2742.3 10843.3,2747.3 10493.3,2767.3 7523.3,2775.81 16137,2776.31 16897,2796.31 8233.3,2855.81 15580.6,2946.31 16146,3014.37 16863.3,3046 17826.6,3046.31 16368.6,3056.31 15853.3,3071.81 1033.3,3072.81 3012,3076.31 3752,3076.31 8219.6,3076.31 7399.6,3086.31 10603.3,3095.81 9703.3,3108.48 15443.3,3111 10433.3,3115.81 15643.3,3270 16358.6,3376.31 4858.6,3386.31 7359.6,3386.31 4903.3,3397.3 10179.6,3436.31 11011.77,3447.8 7182.6,3456.31 9460,3456.31 11139.6,3456.31 16869.6,3471.25 16103.3,3490 7999.6,3506.31 843.3,3539.81 17836.6,3566.31 4927.6,3616.31 7993.3,3619.81 17410.6,3696.31 6323.3,3751.81 10963.3,3760.81 10123.3,3763.81 5694.6,3766.31 7221.6,3766.31 8226.6,3766.31 9440,3766.31 11210.6,3766.31 16319.6,3796.31 3552,3806.47 16123.3,3808 16903.3,3809 16573.3,3812.81 17813.3,3812.81 15963.3,3820.81 757.6,3836.31 15599.6,3836.31 312,3846.47 6240.6,3876.31 5723.3,3878.81 15903.3,3920.81 17583.3,4022.81 16375.6,4026.31 823.3,4235.81 1653.3,4240.81 16122,4256.31 17253.3,4259.81 17845.6,4266.31 16843.3,4272 16363.3,4310.81 3903.3,4340.81 4647.6,4376.31 123.3,4643.81 1291.77,4737.8 7552,4816.31 1318.6,4826.31 5719.6,4826.31 4576.6,4836.31 2463.3,4846.47 5279.6,4846.31 1619.6,4856.31 3160.6,4856.31 6539.6,4856.31 10161.77,4857.8 323.3,4861.81 3983.3,4866.47 7323.3,4865.81 9686.77,4867.8 1893.3,4870.81 6144.6,4876.31 8209.6,4916.31 5501,5049 8186.85,5140.7 7864.6,5186.31 3703.3,5230.81 4423.3,5230.81 6383.3,5240.81 4629.6,5306.31 2986.6,5316.31 3823.3,5340.81 6593.3,5340.81 123.3,5440.81 8664.6,5516.31 9153.3,5530.81
  other v5: 3440,136.31 100,476.31 550,556.31 2550,660 1110,676.31 1760,896.31 3783.3,930 680,956.31 1163.3,990 3043.3,1010 5767,1030 1930,1290 60,1376.31 5777,1380 5777,1440 290,1576.31 1983.3,1590 870,1610 732,1616.31 2447,1636.47 7850,1716.31 8003.3,1720 10503.3,1740 10080,1756.31 70,1816.31 10583.3,1960 10040,1976.31 1303.3,2010 920,2016.31 2343.3,2030 7970,2136.31 263.3,2340 1383.3,2341.47 983.3,2351.47 2227,2351.47 70,2556.31 1063.3,2770 1970,2796.31 2303.3,2840 2003.3,3066.47 130,3076.31 723.3,3120 2750,3516.31 3530,3556.31 1063.3,3580 1910,3580 2750,3816.31
  other v6: 13593.29,256.31 12603.3,393.48 13778.29,396.31 12828.29,416.31 13323.3,468.48 8503.3,643.48 10678.29,643.48 7618.29,649.48 10543.3,853.48 10103.3,858.48 15347,866.47 15222,1016.47 15450.35,1096.31 13069.6,1196.31 15223.3,1226.8 15437.35,1256.31 15313.35,1296.31 14143.3,1521.47 14303.3,1541.47 14463.3,1651.47 14643.3,1666.47 13019.6,1796.31 12683.3,1856.47 12377,1876.31 12712,2176.31 12627,2296.31 12443.3,2301.47 13263.3,2888.48 1703.3,3031.47 15223.3,3284.8 13103.3,3723.48 12883.3,3763.48 13614.6,3796.31 13254.6,3876.31 1923.3,5511.47 5102,5533.97 6247,5533.97 6957,5533.97 7707,5536.31 3583.3,5541.47
  other v11: 5132,976.31 7072,976.31 14767,1205
KB_C0: CN1.40 D4.2 D5.2 D6.2 D7.2 D8.2 D9.2 D10.2 D11.2 D12.2 D13.2 D14.2 | length 20819.3
  Top Layer w8: v2@8582,1513.51 8576.85,1513.51 8576.85,2324.85 8826.85,2574.85 8826.85,3101.3 ; 8826.85,3100.7 8826.85,3101.3 ; 8826.85,3570.7 8826.85,3101.3 ; 8826.85,3571.3 8478.15,3920 8478.15,4410 8563.96,4495.81 9043.02,4495.81 v8@9584.31,5037.1
  Bottom Layer w8: D4.2@854.8,5030 854.9,5029.9 854.9,5018.56 962,4911.47 1602,4911.47 1707.85,5017.32 1707.85,5029.9 1707.95,5030 1708.05,5029.9 1708.05,5015.42 1812,4911.47 3022,4911.47 3127.85,5017.32 3127.85,5029.9 3127.95,5030 3128.05,5029.9 3128.05,5015.42 3232,4911.47 3772,4911.47 3877.85,5017.32 3877.85,5029.9 3877.95,5030 3878.05,5029.9 3878.05,5015.42 3982,4911.47 4522,4911.47 4627.85,5017.32 4627.85,5029.9 4627.95,5030 4628.05,5029.9 4628.05,5020.42 4737,4911.47 5267,4911.47 5372.66,5017.12 5372.66,5029.9 5372.76,5030 5372.85,5029.9 5372.85,5015.61 5477,4911.47 6417,4911.47 6519.5,5013.97 6622,4911.47 7167,4911.47 7267.85,5012.32 7267.85,5029.9 7267.95,5030 7268.05,5029.9 7268.05,5015.42 7372,4911.47 7902,4911.47 8007.85,5017.32 8007.85,5029.9 8007.95,5030 8008.05,5029.9 8008.05,5015.42 8073.47,4950 8700.53,4950 8767.85,5017.32 8767.85,5042.32 8830.34,5104.8 9387,5104.8 9451.8,5040 v8@9581.41,5040 ; D5.2@1712.48,5034.52 D5.2@1717,5030 ; D12.2@8010.55,5032.6 D12.2@8013.15,5030 ; v2(8582,1514.07) 14091.07,1514.07 14497,1920 CN1.40@14567,1920 ; v8@9585.6,5040 9663.57,5040 9723.57,5100 9853.47,5100 9907.95,5045.51 D14.2@9907.95,5030
  other v8: 9585.6,5035.81
KB_C1: CN1.37 D15.2 D16.2 D17.2 D18.2 D19.2 D20.2 D21.2 D22.2 D23.2 D24.2 D25.2 | length 17591.3
  Top Layer w8: v2@8447,3941.47 8447,3915.83 8801.37,3561.47 8801.37,2585.83 8552,2336.47 v2@8552,1536.47
  Bottom Layer w8: D15.2@884.8,4024.8 D15.2@884.8,4003.3 884.8,3986.97 1000.31,3871.47 1602,3871.47 1717.95,3987.42 1838.91,3866.47 2337,3866.47 2462.99,3992.45 2588.98,3866.47 3092,3866.47 3212.76,3987.22 3333.51,3866.47 3842,3866.47 3957.95,3982.42 4023.91,3916.47 4627,3916.47 4702,3991.47 4777,3916.47 5372,3916.47 5446.1,3990.57 5446.1,4005.15 D21.2@5447.95,4007 ; D16.2@1715.32,4024.8 1717.95,4024.8 D16.2@1717.95,4003.3 ; D17.2@2462.99,4003.3 D17.2@2462.99,4030.16 ; D18.2@3212.76,4003.3 D18.2@3212.76,4020.39 ; D19.2@3957.95,4003.3 D19.2@3957.95,4015.2 ; D21.2@5447.95,4003.3 D21.2@5447.95,4007 ; D21.2@5447.95,4025.2 D21.2@5447.95,4007 ; D21.2@5448.55,4006.4 D21.2@5447.95,4007 ; D22.2@6202.76,4003.3 D22.2@6202.76,4029.61 ; D24.2@7692.76,4020.39 D24.2@7692.76,4003.3 ; D24.2@7696.25,3985 7764.79,3916.47 8422,3916.47 8442.76,3937.22 D25.2@8442.76,4003.3 ; D24.2@7711.06,3985 D24.2@7692.76,4003.3 ; v2@8552,1538.07 14080.07,1538.07 14512,1970 14617,1970 CN1.37@14667,2020 ; D21.2@5447.95,4007 5449.8,4005.15 5449.8,3983.66 5517,3916.47 6127,3916.47 6202.76,3992.22 6278.51,3916.47 6872,3916.47 6947,3991.47 7022,3916.47 7622,3916.47 7692.76,3987.22 D24.2@7692.76,4003.3
  other v2: 8547,1536.47 8442,3941.47
KB_C2: CN1.38 D26.2 D27.2 D28.2 D29.2 D30.2 D31.2 D32.2 D33.2 D34.2 D35.2 D36.2 | length 16907.8
  Top Layer w8: v2@8603,1566.47 8603,2319.85 8865.85,2582.7 8865.85,3227.31 v2(8856.85,3236.31)
  Bottom Layer w8: D26.2@884.8,3254.89 884.8,3238.66 1007.16,3116.31 1766.84,3116.31 D27.2@1892,3241.47 ; v2@8607,1562.07 14069.07,1562.07 14527,2020 CN1.38@14567,2020 ; v2(8856.85,3236.31) 8821.34,3236.31 8811.59,3246.05 8737,3171.47 8122,3171.47 D35.2@8052,3241.47 ; D27.2@1892,3241.47 2017.16,3116.31 2686.84,3116.31 2812,3241.47 2937.16,3116.31 3436.84,3116.31 3559.5,3238.97 3672,3126.47 4192,3126.47 4307,3241.47 4422,3126.47 4942,3126.47 5057,3241.47 5172,3126.47 5697,3126.47 5807,3236.47 5917,3126.47 6442,3126.47 D33.2@6557,3241.47 ; D27.2@1892,3241.47 1894.07,3243.54 1894.07,3253.97 1886.78,3246.68 D27.2@1892,3241.47 ; D33.2@6557,3241.47 6627,3171.47 7237,3171.47 D34.2@7307,3241.47 ; D33.2@6557,3241.47 6551.97,3246.5 6559.15,3253.69 6559.15,3243.62 D33.2@6557,3241.47 ; D34.2@7307,3241.47 7377,3171.47 7982,3171.47 D35.2@8052,3241.47 ; D34.2@7307,3241.47 7301,3247.46 7308.19,3254.65 7308.19,3242.65 D34.2@7307,3241.47 ; D35.2@8052,3241.47 8047.52,3245.94 8054.61,3253.03 8054.61,3244.08 D35.2@8052,3241.47
  other v2: 8607,1566.47
KB_C3: CN1.33 D37.2 D38.2 D39.2 D40.2 D41.2 D42.2 D43.2 D44.2 D45.2 D46.2 D47.2 | length 15955.5
  Top Layer w8: v8@8716.3,1676.47 8716.3,2260.77 v2@8894.5,2438.97
  Bottom Layer w8: D37.2@886.89,2507.29 886.89,2491.42 991.84,2386.47 1897,2386.47 2017.82,2507.29 2017.82,2480.65 2072,2426.47 2967,2426.47 3032,2491.47 3097,2426.47 3712,2426.47 3779.5,2493.97 3847,2426.47 4462,2426.47 4532,2496.47 4602,2426.47 5207,2426.47 5272,2491.47 5337,2426.47 5957,2426.47 6024.5,2493.97 6092,2426.47 6702,2426.47 6770.04,2494.5 D44.2@6770.04,2507.29 ; D44.2@6770.04,2486.96 6781.5,2486.96 6842,2426.47 7454.54,2426.47 7520.04,2491.96 7585.53,2426.47 8202,2426.47 8269.5,2493.97 8337,2426.47 8883.47,2426.47 8897,2440 8905.53,2431.47 8957,2431.47 9020.04,2494.5 D47.2@9020.04,2507.29 ; v8(8717,1676.47) 9427,1676.47 9469.39,1634.07 14036.07,1634.07 14517,2115 14517,2241.47 14545.53,2270 14592,2270 14642,2220 CN1.33@14667,2220
  other v2: 8897,2436.47
KB_C4: CN1.36 D48.2 D49.2 D50.2 D51.2 D52.2 D53.2 D54.2 D55.2 D56.2 D57.2 | length 14557.1
  Bottom Layer w8: D48.2@889.87,1760.05 D48.2@890.74,1759.19 890.74,1742.73 957,1676.47 2122,1676.47 2192,1746.47 2262,1676.47 3352,1676.47 3422,1746.47 3483.47,1685 4115.53,1685 D51.2@4174.5,1743.97 ; D53.2@5673.63,1758.93 D53.2@5681.55,1751.01 ; D57.2@8658.69,1759.19 D57.2@8658.69,1735 ; CN1.36@14567,2120 14557,2120 14047.07,1610.07 9447,1610.07 9415.61,1641.47 8707,1641.47 8658.69,1689.78 D57.2@8658.69,1735 ; D51.2@4174.5,1743.97 4168.29,1750.17 4175.59,1757.48 4175.59,1745.06 D51.2@4174.5,1743.97 ; D51.2@4174.5,1743.97 4233.47,1685 4860.53,1685 4922,1746.47 4983.47,1685 5615.53,1685 D53.2@5681.55,1751.01 ; D53.2@5681.55,1751.01 5681.55,1736.92 5733.47,1685 6360.53,1685 D54.2@6419.5,1743.97 ; D54.2@6419.5,1743.97 6420.23,1744.7 6420.23,1758.04 6412.83,1750.64 D54.2@6419.5,1743.97 ; D54.2@6419.5,1743.97 6478.47,1685 7105.53,1685 7167,1746.47 7228.47,1685 7862.92,1685 7920.69,1742.78 7978.47,1685 8590.53,1685 8631.23,1725.7 8639.38,1725.7 8648.69,1735 D57.2@8658.69,1735
KB_C5: CN1.35 D58.2 D59.2 D60.2 D61.2 D62.2 D63.2 | length 15862.6
  Top Layer w8: v2@6353,1315 v2(6353,1318) v2@6353,1410 ; v2(9347,1095) v2@9347,1586.07
  Bottom Layer w8: D58.2@884.8,1011.2 D58.2@884.8,999.47 884.8,993.66 952,926.47 1827,926.47 1884.5,983.97 1942,926.47 2752,926.47 D60.2@2812,986.47 ; D60.2@2807,991.47 D60.2@2812,986.47 ; D60.2@2809.5,998.97 D60.2@2817,991.47 ; D60.2@2819.5,993.97 D60.2@2817,991.47 ; D61.2@3737,981.47 3682,926.47 2872,926.47 D60.2@2812,986.47 ; D61.2@3737.95,997.42 D61.2@3737.95,999.47 D61.2@3737.95,1011.2 ; D61.2@3743.3,1028 3752,1036.7 3752,1346.97 3971,1565.97 5821.74,1565.97 5896.71,1490.99 5896.71,1391.44 5973.15,1315 v2@6353,1315 ; D62.2@6314.43,1012.74 6348.15,1046.47 v2@6348.15,1310 ; v2(6352,1410) 6420.53,1410 6622,1611.47 8440.31,1611.47 8455.51,1596.27 9347.2,1596.27 9357.39,1586.07 14058.07,1586.07 14542,2070 14617,2070 CN1.35@14667,2120 ; D63.2@9347,1033 v2(9347,1095) ; D63.2@9365.98,1011.19 9365.98,1036.47 D63.2@9374.16,1028.29 ; D60.2@2812,986.47 D60.2@2817,991.47
  other v2: 9347,1596.07
KB_C6: CN1.10 D64.2 D65.2 D66.2 D67.2 D68.2 D69.2 D70.2 D71.2 D72.2 | length 8646.6
  Top Layer w8: v2(14552,4990) 14513.29,4951.29 14513.29,3467.38 14560.67,3420 CN1.10@14567,3420
  Bottom Layer w8: D64.2@10655.86,5030 10655.86,5050.33 10705.34,5099.8 10879.45,5099.8 10939.25,5040 11143.15,5040 11214.15,5111 11342.15,5111 11403.76,5049.39 D65.2@11403.76,5035 ; D65.2@11404.06,5030 D65.2@11404.06,5035 ; D65.2@11404.06,5055.91 11416.44,5055.91 11460.53,5100 11627.18,5100 11687.18,5040 11880.53,5040 11935.53,5095 12047.15,5095 12089.75,5052.39 D66.2@12150.76,5052.39 ; D66.2@12150.76,5035 D66.2@12151.98,5035 ; D66.2@12151.98,5030 D66.2@12151.98,5035 ; D68.2@13947.95,5060 13947.95,5078.2 ; v2(14552,4990) 14592,5030 D69.2@14637.95,5030 ; D69.2@14634.9,5033.05 D69.2@14637.95,5030 ; D69.2@14637,5046.47 14583.47,5100 14453.02,5100 14403.47,5050.45 14191.55,5050.45 14142,5100 13969.76,5100 13947.95,5078.2 ; D72.2@16917,4985.2 16852.2,5050 16451.8,5050 D71.2@16387,4985.2 16342.2,5030 15908.02,5030 D70.2@15863.21,4985.2 15818.41,5030 15702.55,5030 15661.85,5070.7 15506.85,5070.7 15486.85,5050.7 15016.85,5050.7 14996.15,5030 D69.2@14637.95,5030 ; D66.2@12151.98,5035 12487,5035 12556.8,5104.8 12658.35,5104.8 12723.15,5040 12902.15,5040 12969.15,5107 13106.47,5107 13172,5041.47 13235.34,5104.8 13417.35,5104.8 13468.15,5054 13683.15,5054 13753.15,5124 13902.15,5124 13947.95,5078.2
KB_C7: CN1.31 D73.2 D74.2 D75.2 D76.2 D77.2 D78.2 D79.2 D80.2 D81.2 D82.2 D83.2 | length 12117.3
  Top Layer w8: v8(14412,3920) 14433.29,3898.71 14433.29,2463.71 14522,2375 14612,2375 CN1.31@14667,2320 ; v8(15396.85,4530.7) 15396.85,4565.7 15446.85,4615.7 15446.85,4805.7 15531.85,4890.7 v8(15531.85,4930.7)
  Bottom Layer w8: D73.2@9197.95,4025.2 D73.2@9197.95,4003.3 9197.95,3985.51 9267,3916.47 9877,3916.47 9947.95,3987.42 10018.91,3916.47 10612,3916.47 10684.5,3988.97 10757,3916.47 11722,3916.47 11793.15,3987.62 D76.2@11793.15,4003.3 11793.15,4017.62 11969.02,4193.48 12539.98,4193.48 12728.47,4005 12922,4005 12992,4075 13113.47,4075 13172.76,4015.71 D77.2@13172.76,4003.3 13172.76,3990.71 13235.66,3927.8 13853.34,3927.8 13917,3991.47 13980.66,3927.8 14404.2,3927.8 v8(14412,3920) 14412,4035 14430.86,4053.86 14430.86,4208.86 14522,4300 14752,4300 14986.48,4534.48 v8@15396.85,4534.48 ; D74.2@9947.95,4003.3 D74.2@9947.95,4024.8 ; D75.2@10687.95,4014.8 D75.2@10687.95,4025.2 ; v8@15401.85,4520.7 15441.85,4480.7 15441.85,4285.7 15856.73,3870.81 16063.96,3870.81 16127.95,3934.8 16127.95,3935.2 16188.15,3875 16823.15,3875 D82.2@16877.95,3929.8 ; v8(15531.85,4930.7) 15531.85,4938.14 D80.2@15589.6,4995.89 ; D82.2@16875.79,3950 D82.2@16875.79,3980.27 ; D82.2@16889.67,3950 D82.2@16877.95,3950 16961.51,3866.45 D83.2@17479.6,3866.45
KB_C8: CN2.6 D84.2 D85.2 D86.2 D87.2 D88.2 D89.2 D90.2 D91.2 D92.2 D93.2 D94.2 | length 10189.5
  Top Layer w8: CN2.6@12167,3820 12167,3800 12217,3750 v2(12217,3270) ; v2(15426.77,3284.89) v2@15561.77,3284.89
  Bottom Layer w8: D84.2@9547.95,3239.05 9615.53,3171.47 10232,3171.47 10297,3236.47 10362,3171.47 11002,3171.47 11067,3236.47 11148.47,3155 11962,3155 12001.8,3194.8 D87.2@12001.8,3260 12001.8,3270 v2(12217,3270) 12357,3270 12482,3145 13107.76,3145 13207.95,3245.2 13278.15,3175 13888.07,3175 D89.2@13967.95,3254.89 14117.84,3105 14339.92,3105 D90.2@14404.8,3169.89 14504.92,3270 14802,3270 14857,3325 15257,3325 15297.11,3284.89 v2(15426.77,3284.89) v2@15433.04,3284.89 ; D91.2@15377.95,3950 15396.85,3931.1 15396.85,3739.15 15556.77,3579.23 15556.77,3255.23 15687,3125 16132,3125 ; D92.2@16132,3219.8 16132,3125 ; D94.2@17489.6,2781.25 17277.22,2781.25 16877.95,3180.51 16877.95,3179.8 16823.15,3125 16132,3125
  other v2: 15561.77,3287.8
KB_C9: CN2.5 D95.2 D96.2 D97.2 D98.2 D99.2 D100.2 | length 9515.8
  Top Layer w8: v2(11807,2510) v2@11807,3530
  Bottom Layer w8: D95.2@9760.04,2507.29 9760.04,2493.43 9827,2426.47 10452,2426.47 D96.2@10519.5,2493.97 ; D97.2@11704.84,2507.29 11704.84,2489.31 11642,2426.47 10587,2426.47 D96.2@10519.5,2493.97 ; D97.2@11712.55,2515 v2@11807,2515 ; v2@11809.5,3532.5 12047,3770 12217,3770 CN2.5@12267,3820 12317,3820 12577,3560 14417,3560 14427,3570 15002,3570 15021.3,3550.7 15293.79,3550.7 15456.77,3387.73 15456.77,3196.38 15848.15,2805 16067,2805 16212,2660 16212,2576.47 16142.95,2507.42 16142.95,2465 D99.2@16127.95,2450 ; D98.2@15377.95,3200 15453.15,3200 ; D99.2@16121.87,2443.92 16195.79,2370 16780.53,2370 16860.53,2450 D100.2@16875.79,2450 ; D100.2@16875.79,2480.27 D100.2@16875.79,2450 ; D100.2@16877.95,2450 D100.2@16875.79,2450 ; D96.2@10519.5,2493.97 10514.84,2498.63 10524.16,2498.63 D96.2@10519.5,2493.97
  other v2: 11812,3530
